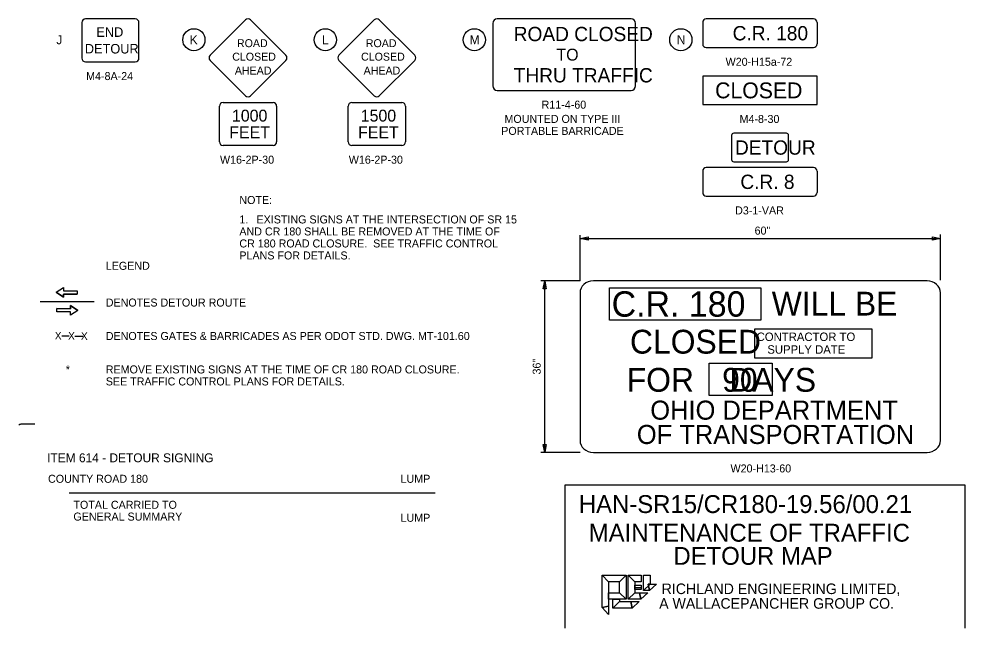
# Model space of a CAD drawing. Extents: x 1633.3 to 1707.6, y 1081.5 to 1106.
# Drawn here: x 1691.04 to 1707.6, y 1085.49 to 1096.15 of the extents above; entities that cross this region are included whole.
import ezdxf

# ---------------------------------------------------------------- set-up
doc = ezdxf.new("R2010")
doc.units = 0
for name, color, linetype in [('GM_X_Interchange_Ramps', 7, 'Continuous'), ('SH_Border', 7, 'Continuous'), ('SH_Data', 7, 'Continuous'), ('SH_Text', 7, 'Continuous'), ('SN_P_Signs', 7, 'Continuous'), ('SN_P_Text', 7, 'Continuous')]:
    doc.layers.add(name, color=color, linetype=linetype)

msp = doc.modelspace()

# ---------------------------------------------------------------- linework, layer by layer
at = {"layer": 'GM_X_Interchange_Ramps'}
msp.add_lwpolyline([(1691.321, 1089.058), (1691.098, 1089.061), (1691.092, 1089.06), (1691.087, 1089.06), (1691.082, 1089.059), (1691.076, 1089.058), (1691.069, 1089.056), (1691.065, 1089.055), (1691.061, 1089.053), (1691.057, 1089.051), (1691.052, 1089.049), (1691.048, 1089.045), (1691.045, 1089.041)], dxfattribs=at)
at = {"layer": 'SH_Border'}
for p, q in [((1707.596, 1087.992), (1700.596, 1087.992)), ((1700.596, 1087.992), (1700.596, 1085.492)), ((1707.596, 1085.492), (1707.596, 1087.992))]:
    msp.add_line(p, q, dxfattribs=at)
at = {"layer": 'SH_Text'}
for p, q in [((1700.86, 1091.566), (1700.86, 1092.364)), ((1700.86, 1092.306), (1707.165, 1092.306)), ((1707.165, 1091.578), (1707.165, 1092.376)), ((1691.697, 1091.366), (1691.825, 1091.45)), ((1691.825, 1091.45), (1691.824, 1091.393)), ((1700.86, 1091.566), (1700.172, 1091.566)), ((1700.242, 1088.566), (1700.242, 1091.566)), ((1691.697, 1091.366), (1691.824, 1091.281)), ((1691.824, 1091.393), (1692.066, 1091.393)), ((1691.824, 1091.281), (1691.824, 1091.335)), ((1691.824, 1091.335), (1692.066, 1091.335)), ((1692.066, 1091.393), (1692.066, 1091.335)), ((1692.36, 1091.198), (1691.417, 1091.198)), ((1691.947, 1091.08), (1691.705, 1091.081)), ((1691.705, 1091.023), (1691.705, 1091.081)), ((1692.074, 1091.05), (1691.947, 1091.135)), ((1691.947, 1091.135), (1691.947, 1091.08)), ((1691.947, 1091.022), (1691.705, 1091.023)), ((1692.074, 1091.05), (1691.947, 1090.965)), ((1691.947, 1090.965), (1691.947, 1091.022)), ((1700.86, 1088.566), (1700.172, 1088.566)), ((1698.327, 1087.851), (1691.921, 1087.851)), ((1701.818, 1086.205), (1701.932, 1086.205))]:
    msp.add_line(p, q, dxfattribs=at)
for points in [[(1701, 1092.278), (1700.86, 1092.306), (1701, 1092.334)], [(1707.025, 1092.334), (1707.165, 1092.306), (1707.025, 1092.278)], [(1692.066, 1091.335), (1691.824, 1091.335), (1691.824, 1091.281), (1691.697, 1091.366), (1691.825, 1091.45), (1691.824, 1091.393), (1692.066, 1091.393)], [(1700.214, 1091.426), (1700.242, 1091.566), (1700.27, 1091.426)], [(1701.374, 1091.447), (1704.022, 1091.447), (1704.022, 1090.878), (1701.374, 1090.878)], [(1691.705, 1091.081), (1691.947, 1091.08), (1691.947, 1091.135), (1692.074, 1091.05), (1691.947, 1090.965), (1691.947, 1091.022), (1691.705, 1091.023)], [(1703.916, 1090.726), (1705.965, 1090.726), (1705.965, 1090.213), (1703.916, 1090.213)], [(1703.121, 1090.127), (1704.223, 1090.127), (1704.223, 1089.563), (1703.121, 1089.563)], [(1700.27, 1088.706), (1700.242, 1088.566), (1700.214, 1088.706)], [(1701.246, 1085.851), (1701.246, 1086.415), (1701.361, 1086.301), (1701.361, 1085.874)], [(1701.246, 1086.415), (1701.665, 1086.415), (1701.551, 1086.301), (1701.361, 1086.301)], [(1701.665, 1086.415), (1701.665, 1085.996), (1701.551, 1086.11), (1701.551, 1086.301)], [(1701.703, 1085.996), (1701.703, 1086.415), (1701.818, 1086.301), (1701.818, 1086.11)], [(1701.703, 1086.415), (1701.932, 1086.415), (1701.932, 1086.301), (1701.818, 1086.301)], [(1701.97, 1086.148), (1701.97, 1086.415), (1702.085, 1086.415), (1702.085, 1086.263)], [(1701.932, 1086.24), (1701.932, 1086.17), (1701.819, 1086.17), (1701.819, 1086.24)], [(1702.077, 1086.148), (1701.97, 1086.148), (1702.085, 1086.263), (1702.054, 1086.263)], [(1702.199, 1086.263), (1702.077, 1086.148), (1702.054, 1086.263)], [(1701.665, 1085.996), (1701.361, 1085.996), (1701.361, 1086.11), (1701.551, 1086.11)], [(1701.437, 1085.843), (1701.437, 1085.996), (1701.551, 1085.996), (1701.551, 1085.957)], [(1701.772, 1085.843), (1701.437, 1085.843), (1701.551, 1085.957), (1701.749, 1085.957)], [(1701.925, 1085.996), (1701.703, 1085.996), (1701.818, 1086.11), (1701.901, 1086.11)], [(1701.894, 1085.957), (1701.772, 1085.843), (1701.749, 1085.957)], [(1702.046, 1086.11), (1701.925, 1085.996), (1701.901, 1086.11)], [(1701.361, 1085.729), (1701.246, 1085.851), (1701.361, 1085.874)]]:
    msp.add_lwpolyline(points, close=True, dxfattribs=at)
for centre in [(1694.105, 1095.784), (1696.404, 1095.784), (1699.012, 1095.784), (1702.624, 1095.784)]:
    msp.add_circle(centre, 0.194, dxfattribs=at)
at = {"layer": 'SN_P_Signs'}
for p, q in [((1706.932, 1091.566), (1701.093, 1091.566)), ((1700.86, 1091.358), (1700.86, 1088.774)), ((1707.165, 1088.774), (1707.165, 1091.358)), ((1691.794, 1090.603), (1691.924, 1090.602)), ((1692.024, 1090.6), (1692.161, 1090.598)), ((1701.093, 1088.566), (1706.932, 1088.566))]:
    msp.add_line(p, q, dxfattribs=at)
for points in [[(1692.145, 1096.084), (1692.145, 1095.464)], [(1693.08, 1096.149), (1692.21, 1096.149)], [(1693.145, 1095.464), (1693.145, 1096.084)], [(1694.389, 1095.512), (1695.008, 1096.131)], [(1695.096, 1096.131), (1695.715, 1095.512)], [(1696.642, 1095.512), (1697.261, 1096.131)], [(1697.349, 1096.131), (1697.968, 1095.512)], [(1699.333, 1096.071), (1699.333, 1094.977)], [(1701.755, 1096.149), (1699.411, 1096.149)], [(1701.833, 1094.977), (1701.833, 1096.071)], [(1703.006, 1096.086), (1703.006, 1095.711)], [(1704.944, 1096.149), (1703.069, 1096.149)], [(1705.006, 1096.086), (1705.006, 1095.711)], [(1703.069, 1095.649), (1704.944, 1095.649)], [(1692.21, 1095.399), (1693.08, 1095.399)], [(1695.008, 1094.805), (1694.389, 1095.423)], [(1695.715, 1095.423), (1695.096, 1094.805)], [(1697.261, 1094.805), (1696.642, 1095.423)], [(1697.968, 1095.423), (1697.349, 1094.805)], [(1699.411, 1094.899), (1701.755, 1094.899)], [(1694.552, 1093.999), (1694.552, 1094.624)], [(1694.615, 1094.686), (1695.49, 1094.686)], [(1695.552, 1094.624), (1695.552, 1093.999)], [(1696.805, 1093.999), (1696.805, 1094.624)], [(1696.868, 1094.686), (1697.743, 1094.686)], [(1697.805, 1094.624), (1697.805, 1093.999)], [(1703.51, 1094.109), (1703.51, 1093.689)], [(1704.47, 1094.149), (1703.55, 1094.149)], [(1704.51, 1093.689), (1704.51, 1094.109)], [(1695.49, 1093.936), (1694.615, 1093.936)], [(1697.743, 1093.936), (1696.868, 1093.936)], [(1703.55, 1093.649), (1704.47, 1093.649)], [(1703.006, 1093.486), (1703.006, 1093.111)], [(1704.944, 1093.549), (1703.069, 1093.549)], [(1705.006, 1093.486), (1705.006, 1093.111)], [(1703.069, 1093.049), (1704.944, 1093.049)]]:
    msp.add_lwpolyline(points, dxfattribs=at)
msp.add_lwpolyline([(1703.01, 1094.649), (1705.01, 1094.649), (1705.01, 1095.149), (1703.01, 1095.149)], close=True, dxfattribs=at)
for centre, radius, start, end in [((1692.21, 1096.084), 0.065, 90, 180), ((1693.08, 1096.084), 0.065, 0, 90), ((1695.052, 1096.086), 0.0625, 45, 135), ((1697.305, 1096.086), 0.0625, 45, 135), ((1699.411, 1096.071), 0.0781, 90, 180), ((1701.755, 1096.071), 0.0781, 0, 90), ((1703.069, 1096.086), 0.0625, 90, 180), ((1704.944, 1096.086), 0.0625, 0, 90), ((1703.069, 1095.711), 0.0625, 180, 270), ((1704.944, 1095.711), 0.0625, 270, 0), ((1692.21, 1095.464), 0.065, 180, 270), ((1693.08, 1095.464), 0.065, 270, 0), ((1694.433, 1095.468), 0.0625, 135, 225), ((1695.671, 1095.468), 0.0625, 315, 45), ((1696.686, 1095.468), 0.0625, 135, 225), ((1697.924, 1095.468), 0.0625, 315, 45), ((1699.411, 1094.977), 0.0781, 180, 270), ((1701.755, 1094.977), 0.0781, 270, 0), ((1695.052, 1094.849), 0.0625, 225, 315), ((1697.305, 1094.849), 0.0625, 225, 315), ((1694.615, 1094.624), 0.0625, 90, 180), ((1695.49, 1094.624), 0.0625, 0, 90), ((1696.868, 1094.624), 0.0625, 90, 180), ((1697.743, 1094.624), 0.0625, 0, 90), ((1703.55, 1094.109), 0.04, 90, 180), ((1704.47, 1094.109), 0.04, 0, 90), ((1694.615, 1093.999), 0.0625, 180, 270), ((1695.49, 1093.999), 0.0625, 270, 0), ((1696.868, 1093.999), 0.0625, 180, 270), ((1697.743, 1093.999), 0.0625, 270, 0), ((1703.55, 1093.689), 0.04, 180, 270), ((1704.47, 1093.689), 0.04, 270, 0), ((1703.069, 1093.486), 0.0625, 90, 180), ((1704.944, 1093.486), 0.0625, 0, 90), ((1703.069, 1093.111), 0.0625, 180, 270), ((1704.944, 1093.111), 0.0625, 270, 0)]:
    msp.add_arc(centre, radius, start, end, dxfattribs=at)
for centre, major_axis, start_param, end_param in [((1701.093, 1091.358), (-0.233, 0), 4.712389, 6.283185), ((1706.932, 1091.358), (0.233, 0), 0, 1.570796), ((1701.093, 1088.774), (-0.233, 0), 0, 1.570796), ((1706.932, 1088.774), (0.233, 0), 4.712389, 6.283185)]:
    msp.add_ellipse(centre, major_axis=major_axis, ratio=0.891693, start_param=start_param, end_param=end_param, dxfattribs=at)

# ---------------------------------------------------------------- texts
at = {"layer": 'SH_Data'}
for s, p in [('HAN-SR15/CR180-19.56/00.21', (1700.84, 1087.505)), ('MAINTENANCE OF TRAFFIC', (1701.013, 1087.004)), ('DETOUR MAP', (1702.494, 1086.599))]:
    msp.add_text(s, height=0.3125, rotation=360, dxfattribs=at).set_placement(p)
at = {"layer": 'SH_Text'}
for s, height, p in [('J', 0.156, (1691.698, 1095.706)), ('K', 0.156, (1694.032, 1095.706)), ('L', 0.156, (1696.347, 1095.706)), ('M', 0.156, (1698.93, 1095.706)), ('N', 0.156, (1702.554, 1095.706)), ('NOTE:', 0.14, (1694.901, 1092.911)), ('1.', 0.14, (1694.901, 1092.571)), ('EXISTING SIGNS AT THE INTERSECTION OF SR 15', 0.14, (1695.201, 1092.571)), ('AND CR 180 SHALL BE REMOVED AT THE TIME OF', 0.14, (1694.901, 1092.361)), ('60"', 0.14, (1703.914, 1092.376)), ('CR 180 ROAD CLOSURE.  SEE TRAFFIC CONTROL', 0.14, (1694.901, 1092.151)), ('PLANS FOR DETAILS.', 0.14, (1694.901, 1091.941)), ('LEGEND', 0.14, (1692.564, 1091.76)), ('DENOTES DETOUR ROUTE', 0.14, (1692.564, 1091.117)), ('C.R. 180', 0.4437, (1701.413, 1090.94)), ('WILL BE', 0.4167, (1704.214, 1090.96)), ('DENOTES GATES & BARRICADES AS PER ODOT STD. DWG. MT-101.60', 0.14, (1692.564, 1090.532)), ('CLOSED', 0.4167, (1701.734, 1090.294)), ('CONTRACTOR TO', 0.14793, (1703.95, 1090.514)), ('SUPPLY DATE', 0.14793, (1704.137, 1090.292)), ('*', 0.14, (1691.864, 1089.947)), ('REMOVE EXISTING SIGNS AT THE TIME OF CR 180 ROAD CLOSURE.', 0.14, (1692.564, 1089.947)), ('FOR    DAYS', 0.41667, (1701.677, 1089.627)), ('90', 0.4167, (1703.346, 1089.627)), ('SEE TRAFFIC CONTROL PLANS FOR DETAILS.', 0.14, (1692.564, 1089.737)), ('ITEM 614 - DETOUR SIGNING', 0.156, (1691.538, 1088.393)), ('W20-H13-60', 0.14, (1703.493, 1088.215)), ('COUNTY ROAD 180', 0.14, (1691.554, 1088.034)), ('LUMP', 0.14, (1697.721, 1088.034)), ('TOTAL CARRIED TO', 0.14, (1691.998, 1087.579)), ('GENERAL SUMMARY', 0.14, (1691.998, 1087.373)), ('LUMP', 0.14, (1697.721, 1087.352))]:
    msp.add_text(s, height=height, dxfattribs=at).set_placement(p)
for s, height, rotation, p in [('36"', 0.14, 90, (1700.172, 1089.928)), ('RICHLAND ENGINEERING LIMITED,', 0.1849, 360, (1702.288, 1086.087)), ('A WALLACEPANCHER GROUP CO.', 0.1849, 360, (1702.245, 1085.831))]:
    msp.add_text(s, height=height, rotation=rotation, dxfattribs=at).set_placement(p)
at = {"layer": 'SN_P_Signs'}
for s, height, p in [('END', 0.1667, (1692.4, 1095.835)), ('ROAD CLOSED', 0.25, (1699.7, 1095.76)), ('C.R. 180', 0.25, (1703.53, 1095.774)), ('ROAD', 0.1389, (1694.859, 1095.655)), ('ROAD', 0.1389, (1697.113, 1095.655)), ('DETOUR', 0.1667, (1692.198, 1095.544)), ('CLOSED', 0.1389, (1694.776, 1095.419)), ('CLOSED', 0.1389, (1697.03, 1095.419)), ('TO', 0.2083, (1700.448, 1095.42)), ('AHEAD', 0.1389, (1694.822, 1095.176)), ('AHEAD', 0.1389, (1697.075, 1095.176)), ('THRU TRAFFIC', 0.25, (1699.7, 1095.038)), ('CLOSED', 0.2778, (1703.223, 1094.76)), ('1000', 0.2083, (1694.771, 1094.353)), ('1500', 0.2083, (1697.024, 1094.353)), ('FEET', 0.2083, (1694.724, 1094.061)), ('FEET', 0.2083, (1696.977, 1094.061)), ('DETOUR', 0.25, (1703.571, 1093.774)), ('C.R. 8', 0.25, (1703.665, 1093.174)), ('OHIO DEPARTMENT', 0.33317, (1702.089, 1089.138)), ('OF TRANSPORTATION', 0.33317, (1701.854, 1088.713))]:
    msp.add_text(s, height=height, dxfattribs=at).set_placement(p)
for p in [(1691.671, 1090.541), (1691.904, 1090.538), (1692.128, 1090.535)]:
    msp.add_text('X', height=0.133, rotation=359.2514, dxfattribs=at).set_placement(p)
at = {"layer": 'SN_P_Text'}
for s, p in [('W20-H15a-72', (1703.407, 1095.329)), ('M4-8A-24', (1692.22, 1095.079)), ('R11-4-60', (1700.188, 1094.579)), ('MOUNTED ON TYPE III', (1699.538, 1094.33)), ('M4-8-30', (1703.651, 1094.329)), ('PORTABLE BARRICADE', (1699.482, 1094.12)), ('W16-2P-30', (1694.562, 1093.616)), ('W16-2P-30', (1696.815, 1093.616)), ('D3-1-VAR', (1703.573, 1092.729))]:
    msp.add_text(s, height=0.14, dxfattribs=at).set_placement(p)

doc.saveas('drawing.dxf')
